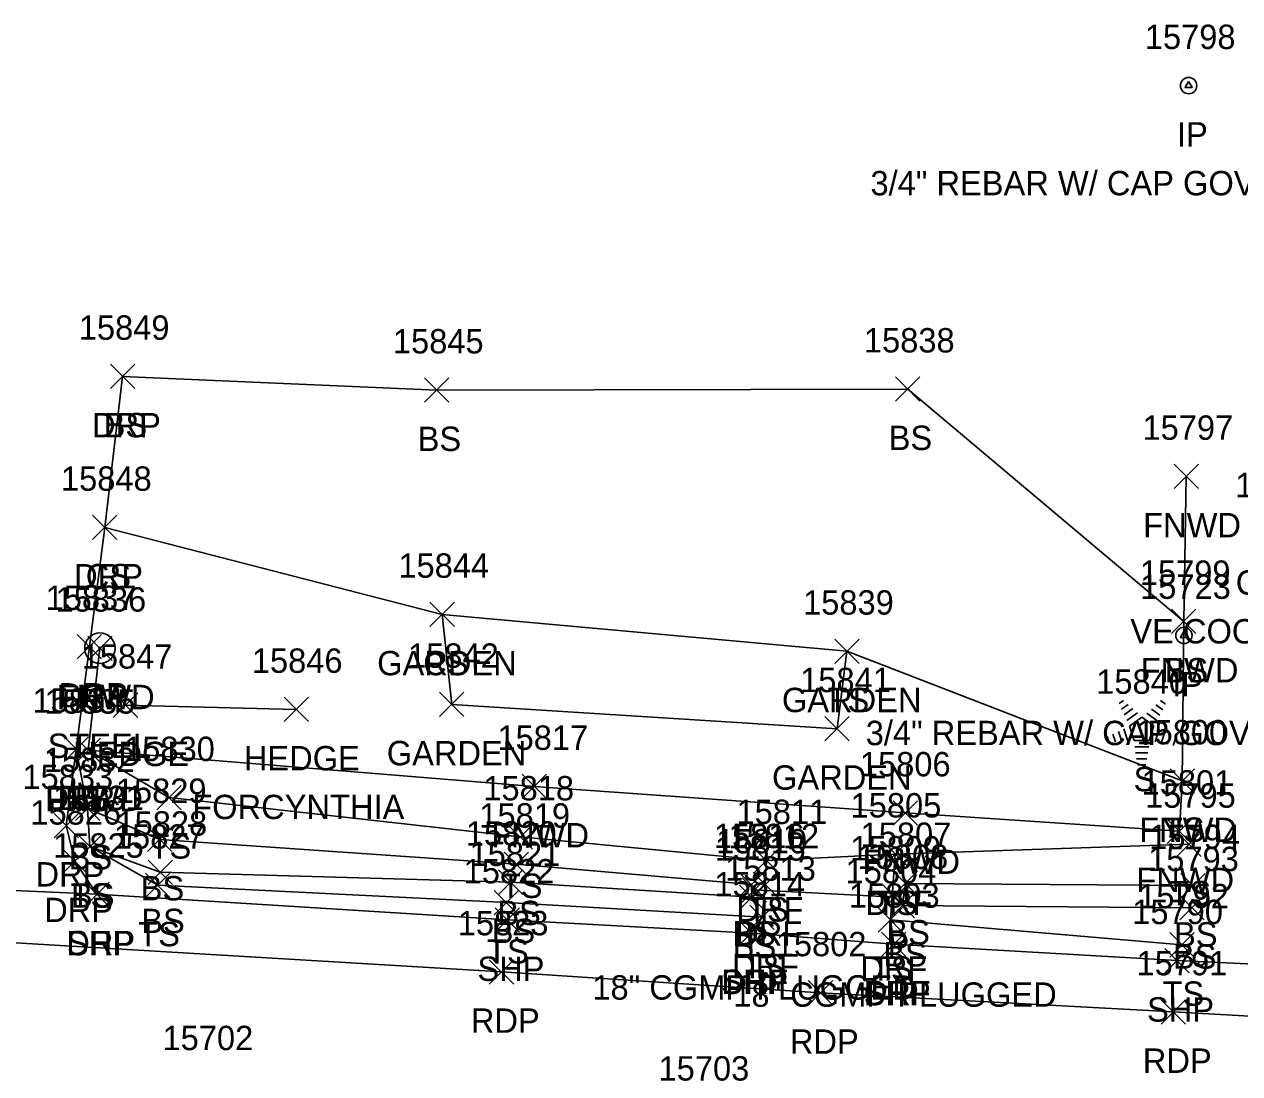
# Model space of a CAD drawing. Extents: x 1606530 to 1613020, y 784959 to 789666.
# Drawn here: x 1609586.7 to 1609686.4, y 788435.4 to 788521.5 of the extents above; entities that cross this region are included whole.
import ezdxf

# ---------------------------------------------------------------- set-up
doc = ezdxf.new("R2010")
doc.units = 0
for name, color, linetype in [('D_A', 7, 'Continuous'), ('D_C', 7, 'Continuous'), ('D_I', 7, 'Continuous'), ('D_TIC', 7, 'Continuous'), ('DCP', 7, 'Continuous'), ('L_A', 7, 'Continuous'), ('L_C', 7, 'Continuous'), ('L_I', 7, 'Continuous'), ('L_TIC', 7, 'Continuous'), ('LAHR', 7, 'Continuous'), ('LAPB', 7, 'Continuous'), ('LELB', 7, 'Continuous'), ('LFNC', 7, 'Continuous'), ('LTC', 7, 'Continuous'), ('M_A', 7, 'Continuous'), ('M_C', 7, 'Continuous'), ('M_I', 7, 'Continuous'), ('MPIR', 7, 'Continuous'), ('P_A', 7, 'Continuous'), ('P_I', 7, 'Continuous'), ('P_TIC', 7, 'Continuous'), ('PET', 7, 'Continuous'), ('PSP', 7, 'Continuous'), ('R_A', 7, 'Continuous'), ('R_I', 7, 'Continuous'), ('R_TIC', 7, 'Continuous'), ('RDF', 7, 'Continuous'), ('RDP', 7, 'Continuous'), ('RGP', 7, 'Continuous'), ('U_A', 7, 'Continuous'), ('U_C', 7, 'Continuous'), ('U_I', 7, 'Continuous')]:
    doc.layers.add(name, color=color, linetype=linetype)

msp = doc.modelspace()

# ---------------------------------------------------------------- linework, layer by layer
at = {"layer": 'D_TIC'}
for points in [[(1609645.563, 788449.455), (1609647.563, 788451.455)], [(1609647.563, 788449.455), (1609645.563, 788451.455)], [(1609657.117, 788448.869), (1609659.117, 788450.869)], [(1609659.117, 788448.869), (1609657.117, 788450.869)]]:
    msp.add_lwpolyline(points, dxfattribs=at)
at = {"layer": 'DCP'}
msp.add_lwpolyline([(1609658.117, 788449.869), (1609646.563, 788450.455)], dxfattribs=at)
at = {"layer": 'L_TIC'}
for points in [[(1609593.795, 788491.58), (1609595.795, 788493.58)], [(1609595.795, 788491.58), (1609593.795, 788493.58)], [(1609619.536, 788490.457), (1609621.536, 788492.457)], [(1609621.536, 788490.457), (1609619.536, 788492.457)], [(1609658.146, 788490.537), (1609660.146, 788492.537)], [(1609660.146, 788490.537), (1609658.146, 788492.537)], [(1609680.978, 788483.374), (1609682.978, 788485.374)], [(1609682.978, 788483.374), (1609680.978, 788485.374)], [(1609592.327, 788479.193), (1609594.327, 788481.193)], [(1609594.327, 788479.193), (1609592.327, 788481.193)], [(1609619.986, 788472.059), (1609621.986, 788474.059)], [(1609621.986, 788472.059), (1609619.986, 788474.059)], [(1609619.986, 788472.059), (1609621.986, 788474.059)], [(1609621.986, 788472.059), (1609619.986, 788474.059)], [(1609619.986, 788472.059), (1609621.986, 788474.059)], [(1609621.986, 788472.059), (1609619.986, 788474.059)], [(1609680.771, 788471.478), (1609682.771, 788473.478)], [(1609682.771, 788471.478), (1609680.771, 788473.478)], [(1609680.771, 788471.478), (1609682.771, 788473.478)], [(1609682.771, 788471.478), (1609680.771, 788473.478)], [(1609591.931, 788469.281), (1609593.931, 788471.281)], [(1609593.931, 788469.281), (1609591.931, 788471.281)], [(1609653.166, 788469.035), (1609655.166, 788471.035)], [(1609655.166, 788469.035), (1609653.166, 788471.035)], [(1609653.166, 788469.035), (1609655.166, 788471.035)], [(1609655.166, 788469.035), (1609653.166, 788471.035)], [(1609653.166, 788469.035), (1609655.166, 788471.035)], [(1609655.166, 788469.035), (1609653.166, 788471.035)], [(1609620.774, 788464.676), (1609622.774, 788466.676)], [(1609622.774, 788464.676), (1609620.774, 788466.676)], [(1609594.027, 788464.611), (1609596.027, 788466.611)], [(1609596.027, 788464.611), (1609594.027, 788466.611)], [(1609608.027, 788464.26), (1609610.027, 788466.26)], [(1609610.027, 788464.26), (1609608.027, 788466.26)], [(1609652.354, 788462.676), (1609654.354, 788464.676)], [(1609654.354, 788462.676), (1609652.354, 788464.676)], [(1609589.993, 788461.002), (1609591.993, 788463.002)], [(1609591.993, 788461.002), (1609589.993, 788463.002)], [(1609590.974, 788460.913), (1609592.974, 788462.913)], [(1609592.974, 788460.913), (1609590.974, 788462.913)], [(1609590.974, 788460.913), (1609592.974, 788462.913)], [(1609592.974, 788460.913), (1609590.974, 788462.913)], [(1609627.538, 788457.943), (1609629.538, 788459.943)], [(1609629.538, 788457.943), (1609627.538, 788459.943)], [(1609680.655, 788458.395), (1609682.655, 788460.395)], [(1609682.655, 788458.395), (1609680.655, 788460.395)], [(1609680.655, 788458.395), (1609682.655, 788460.395)], [(1609682.655, 788458.395), (1609680.655, 788460.395)], [(1609597.591, 788457.025), (1609599.591, 788459.025)], [(1609599.591, 788457.025), (1609597.591, 788459.025)], [(1609590.926, 788456.136), (1609592.926, 788458.136)], [(1609592.926, 788456.136), (1609590.926, 788458.136)], [(1609590.926, 788456.136), (1609592.926, 788458.136)], [(1609592.926, 788456.136), (1609590.926, 788458.136)], [(1609657.95, 788455.77), (1609659.95, 788457.77)], [(1609659.95, 788455.77), (1609657.95, 788457.77)], [(1609626.381, 788453.797), (1609628.381, 788455.797)], [(1609628.381, 788453.797), (1609626.381, 788455.797)], [(1609680.417, 788454.272), (1609682.417, 788456.272)], [(1609682.417, 788454.272), (1609680.417, 788456.272)], [(1609591.115, 788453.005), (1609593.115, 788455.005)], [(1609593.115, 788453.005), (1609591.115, 788455.005)], [(1609591.115, 788453.005), (1609593.115, 788455.005)], [(1609593.115, 788453.005), (1609591.115, 788455.005)], [(1609596.833, 788453.593), (1609598.833, 788455.593)], [(1609598.833, 788453.593), (1609596.833, 788455.593)], [(1609681.194, 788453.195), (1609683.194, 788455.195)], [(1609683.194, 788453.195), (1609681.194, 788455.195)], [(1609646.569, 788451.861), (1609648.569, 788453.861)], [(1609648.569, 788451.861), (1609646.569, 788453.861)], [(1609657.131, 788452.395), (1609659.131, 788454.395)], [(1609659.131, 788452.395), (1609657.131, 788454.395)], [(1609596.876, 788450.909), (1609598.876, 788452.909)], [(1609598.876, 788450.909), (1609596.876, 788452.909)], [(1609626.062, 788451.564), (1609628.062, 788453.564)], [(1609628.062, 788451.564), (1609626.062, 788453.564)], [(1609596.666, 788449.835), (1609598.666, 788451.835)], [(1609598.666, 788449.835), (1609596.666, 788451.835)], [(1609625.602, 788450.09), (1609627.602, 788452.09)], [(1609627.602, 788450.09), (1609625.602, 788452.09)], [(1609645.331, 788449.894), (1609647.331, 788451.894)], [(1609647.331, 788449.894), (1609645.331, 788451.894)], [(1609657.952, 788449.984), (1609659.952, 788451.984)], [(1609659.952, 788449.984), (1609657.952, 788451.984)], [(1609681.534, 788449.809), (1609683.534, 788451.809)], [(1609683.534, 788449.809), (1609681.534, 788451.809)], [(1609645.365, 788448.857), (1609647.365, 788450.857)], [(1609647.365, 788448.857), (1609645.365, 788450.857)], [(1609645.365, 788448.857), (1609647.365, 788450.857)], [(1609647.365, 788448.857), (1609645.365, 788450.857)], [(1609625.255, 788448.415), (1609627.255, 788450.415)], [(1609627.255, 788448.415), (1609625.255, 788450.415)], [(1609657.7, 788448.177), (1609659.7, 788450.177)], [(1609659.7, 788448.177), (1609657.7, 788450.177)], [(1609657.7, 788448.177), (1609659.7, 788450.177)], [(1609659.7, 788448.177), (1609657.7, 788450.177)], [(1609681.444, 788447.994), (1609683.444, 788449.994)], [(1609683.444, 788447.994), (1609681.444, 788449.994)], [(1609646.206, 788447.208), (1609648.206, 788449.208)], [(1609648.206, 788447.208), (1609646.206, 788449.208)], [(1609656.725, 788447), (1609658.725, 788449)], [(1609658.725, 788447), (1609656.725, 788449)], [(1609680.624, 788444.951), (1609682.624, 788446.951)], [(1609682.624, 788444.951), (1609680.624, 788446.951)]]:
    msp.add_lwpolyline(points, dxfattribs=at)
at = {"layer": 'LAHR'}
msp.add_lwpolyline([(1609609.027, 788465.26), (1609595.027, 788465.611)], dxfattribs=at)
at = {"layer": 'LAPB'}
for points in [[(1609654.166, 788470.035), (1609653.354, 788463.676), (1609621.774, 788465.676), (1609620.986, 788473.059)], [(1609654.166, 788470.035), (1609620.986, 788473.059)]]:
    msp.add_lwpolyline(points, dxfattribs=at)
at = {"layer": 'LELB'}
for points in [[(1609681.771, 788472.478), (1609659.146, 788491.537), (1609620.536, 788491.457), (1609594.795, 788492.58)], [(1609620.986, 788473.059), (1609593.327, 788480.193)], [(1609681.655, 788459.395), (1609654.166, 788470.035)], [(1609646.365, 788449.857), (1609626.602, 788451.09), (1609597.876, 788451.909), (1609592.115, 788454.005), (1609591.926, 788457.136), (1609590.993, 788462.002)], [(1609647.569, 788452.861), (1609627.381, 788454.797), (1609598.591, 788458.025), (1609591.974, 788461.913)], [(1609646.365, 788449.857), (1609646.331, 788450.894), (1609627.062, 788452.564), (1609597.833, 788454.593), (1609591.926, 788457.136)], [(1609647.206, 788448.208), (1609626.255, 788449.415), (1609597.666, 788450.835), (1609592.115, 788454.005)], [(1609682.194, 788454.195), (1609658.131, 788453.395)], [(1609682.534, 788450.809), (1609658.952, 788450.984), (1609658.7, 788449.177)], [(1609682.444, 788448.994), (1609658.7, 788449.177)], [(1609681.624, 788445.951), (1609657.725, 788448)]]:
    msp.add_lwpolyline(points, dxfattribs=at)
at = {"layer": 'LFNC'}
msp.add_lwpolyline([(1609681.978, 788484.374), (1609681.771, 788472.478), (1609681.655, 788459.395), (1609681.417, 788455.272), (1609658.95, 788456.77), (1609628.538, 788458.943), (1609591.974, 788461.913), (1609592.931, 788470.281)], dxfattribs=at)
at = {"layer": 'LTC'}
for p, q in [((1609676.47, 788465.748), (1609676.825, 788466.005)), ((1609676.68, 788465.282), (1609677.209, 788465.666)), ((1609679.869, 788465.988), (1609680.288, 788465.683)), ((1609676.889, 788464.816), (1609677.593, 788465.328)), ((1609677.099, 788464.35), (1609677.977, 788464.988)), ((1609678.755, 788464.943), (1609679.565, 788464.354)), ((1609679.127, 788465.291), (1609679.806, 788464.798)), ((1609679.497, 788465.64), (1609680.047, 788465.24)), ((1609676.869, 788463.676), (1609677.2, 788462.657)), ((1609677.324, 788463.895), (1609678.335, 788464.63)), ((1609677.324, 788463.895), (1609677.711, 788462.702)), ((1609678.335, 788464.63), (1609679.332, 788463.905)), ((1609679.332, 788463.905), (1609678.941, 788462.702)), ((1609675.503, 788463.027), (1609675.655, 788462.559)), ((1609675.958, 788463.243), (1609676.17, 788462.592)), ((1609676.414, 788463.46), (1609676.685, 788462.625)), ((1609678.941, 788462.702), (1609677.711, 788462.702)), ((1609679.77, 788463.634), (1609679.432, 788462.595)), ((1609680.214, 788463.384), (1609679.927, 788462.499)), ((1609680.659, 788463.134), (1609680.422, 788462.404)), ((1609681.103, 788462.883), (1609680.917, 788462.309)), ((1609678.903, 788462.202), (1609677.758, 788462.202)), ((1609678.819, 788461.702), (1609677.831, 788461.702)), ((1609678.735, 788461.202), (1609677.904, 788461.202)), ((1609678.652, 788460.702), (1609677.977, 788460.702))]:
    msp.add_line(p, q, dxfattribs=at)
at = {"layer": 'MPIR'}
for points in [[(1609682.172, 788516.762), (1609681.883, 788516.262), (1609682.46, 788516.262)], [(1609681.784, 788471.663), (1609681.495, 788471.163), (1609682.073, 788471.163)]]:
    msp.add_lwpolyline(points, close=True, dxfattribs=at)
for centre in [(1609682.172, 788516.429), (1609681.784, 788471.329)]:
    msp.add_circle(centre, 0.667, dxfattribs=at)
at = {"layer": 'P_TIC'}
for points in [[(1609591.684, 788449.096), (1609593.684, 788451.096)], [(1609593.684, 788449.096), (1609591.684, 788451.096)], [(1609625.337, 788446.989), (1609627.337, 788448.989)], [(1609627.337, 788446.989), (1609625.337, 788448.989)], [(1609645.319, 788445.917), (1609647.319, 788447.917)], [(1609647.319, 788445.917), (1609645.319, 788447.917)], [(1609656.996, 788444.994), (1609658.996, 788446.994)], [(1609658.996, 788444.994), (1609656.996, 788446.994)], [(1609680.225, 788443.652), (1609682.225, 788445.652)], [(1609682.225, 788443.652), (1609680.225, 788445.652)], [(1609624.849, 788442.733), (1609626.849, 788444.733)], [(1609626.849, 788442.733), (1609624.849, 788444.733)], [(1609650.997, 788441.015), (1609652.997, 788443.015)], [(1609652.997, 788441.015), (1609650.997, 788443.015)], [(1609679.929, 788439.448), (1609681.929, 788441.448)], [(1609681.929, 788439.448), (1609679.929, 788441.448)]]:
    msp.add_lwpolyline(points, dxfattribs=at)
at = {"layer": 'PET'}
msp.add_lwpolyline([(1609713.165, 788438.627), (1609680.929, 788440.448), (1609651.997, 788442.015), (1609625.849, 788443.733), (1609580.961, 788446.419), (1609565.084, 788447.467), (1609525.711, 788449.455), (1609486.159, 788451.542), (1609451.915, 788453.585), (1609423.874, 788454.943), (1609378.56, 788456.924), (1609332.013, 788457.666), (1609286.402, 788456.921), (1609233.035, 788453.523), (1609189.077, 788447.384), (1609175.759, 788445.193), (1609148.778, 788439.997), (1609127.707, 788434.803)], dxfattribs=at)
at = {"layer": 'PSP'}
msp.add_lwpolyline([(1609713.922, 788443.117), (1609681.225, 788444.652), (1609657.996, 788445.994), (1609646.319, 788446.917), (1609626.337, 788447.989), (1609592.684, 788450.096), (1609566.898, 788451.268), (1609526.223, 788453.589), (1609486.022, 788455.2), (1609451.52, 788457.024), (1609423.816, 788458.463), (1609378.085, 788460.467), (1609331.883, 788461.682), (1609285.229, 788461.605), (1609232.595, 788457.915), (1609188.508, 788451.364), (1609172.5, 788448.52), (1609147.32, 788443.745), (1609126.968, 788439.128), (1609114.118, 788436.455)], dxfattribs=at)
at = {"layer": 'R_TIC'}
for points in [[(1609593.795, 788491.58), (1609595.795, 788493.58)], [(1609595.795, 788491.58), (1609593.795, 788493.58)], [(1609592.327, 788479.193), (1609594.327, 788481.193)], [(1609594.327, 788479.193), (1609592.327, 788481.193)], [(1609591.073, 788469.419), (1609593.073, 788471.419)], [(1609593.073, 788469.419), (1609591.073, 788471.419)], [(1609589.993, 788461.002), (1609591.993, 788463.002)], [(1609591.993, 788461.002), (1609589.993, 788463.002)], [(1609589.167, 788454.734), (1609591.167, 788456.734)], [(1609591.167, 788454.734), (1609589.167, 788456.734)], [(1609589.874, 788451.812), (1609591.874, 788453.812)], [(1609591.874, 788451.812), (1609589.874, 788453.812)], [(1609646.569, 788451.861), (1609648.569, 788453.861)], [(1609648.569, 788451.861), (1609646.569, 788453.861)], [(1609657.131, 788452.395), (1609659.131, 788454.395)], [(1609659.131, 788452.395), (1609657.131, 788454.395)], [(1609646.472, 788449.879), (1609648.472, 788451.879)], [(1609648.472, 788449.879), (1609646.472, 788451.879)], [(1609591.684, 788449.096), (1609593.684, 788451.096)], [(1609593.684, 788449.096), (1609591.684, 788451.096)], [(1609646.206, 788447.208), (1609648.206, 788449.208)], [(1609648.206, 788447.208), (1609646.206, 788449.208)], [(1609656.725, 788447), (1609658.725, 788449)], [(1609658.725, 788447), (1609656.725, 788449)], [(1609645.319, 788445.917), (1609647.319, 788447.917)], [(1609647.319, 788445.917), (1609645.319, 788447.917)], [(1609656.996, 788444.994), (1609658.996, 788446.994)], [(1609658.996, 788444.994), (1609656.996, 788446.994)]]:
    msp.add_lwpolyline(points, dxfattribs=at)
at = {"layer": 'RDF'}
msp.add_lwpolyline([(1609657.996, 788445.994), (1609657.725, 788448), (1609658.131, 788453.395), (1609647.569, 788452.861), (1609647.472, 788450.879), (1609647.206, 788448.208), (1609646.319, 788446.917)], dxfattribs=at)
at = {"layer": 'RDP'}
msp.add_lwpolyline([(1609592.684, 788450.096), (1609590.874, 788452.812), (1609590.167, 788455.734), (1609590.993, 788462.002), (1609592.073, 788470.419), (1609593.327, 788480.193), (1609594.795, 788492.58)], dxfattribs=at)
at = {"layer": 'RGP'}
msp.add_line((1609592.931, 788470.281), (1609592.931, 788470.281), dxfattribs=at)
for radius in [1.25, 0.0833]:
    msp.add_circle((1609592.931, 788470.281), radius, dxfattribs=at)

# ---------------------------------------------------------------- texts
at = {"layer": 'D_A'}
for p in [(1609645.941, 788445.455), (1609657.495, 788444.869)]:
    msp.add_text('P', height=2, dxfattribs=at).set_placement(p)
at = {"layer": 'D_C'}
for p in [(1609633.296, 788441.455), (1609644.849, 788440.869)]:
    msp.add_text('18" CGMP PLUGGED', height=2, dxfattribs=at).set_placement(p)
at = {"layer": 'D_I'}
for s, p in [('15810', (1609643.453, 788453.455)), ('15809', (1609654.44, 788452.869))]:
    msp.add_text(s, height=2, dxfattribs=at).set_placement(p)
at = {"layer": 'L_A'}
for s, p in [('BS', (1609593.236, 788487.58)), ('BS', (1609618.977, 788486.457)), ('BS', (1609657.587, 788486.537)), ('FNWD', (1609678.443, 788479.374)), ('CS', (1609591.768, 788475.193)), ('GARDEN', (1609615.655, 788468.059)), ('GARDEN', (1609615.655, 788468.059)), ('CS', (1609619.427, 788468.059)), ('FNWD', (1609678.235, 788467.478)), ('BS', (1609680.212, 788467.478)), ('FNWD', (1609589.396, 788465.281)), ('GARDEN', (1609648.836, 788465.035)), ('GARDEN', (1609648.836, 788465.035)), ('TS', (1609652.576, 788465.035)), ('GARDEN', (1609616.443, 788460.676)), ('HEDGE', (1609590.728, 788460.611)), ('HEDGE', (1609604.728, 788460.26)), ('GARDEN', (1609648.023, 788458.676)), ('S', (1609677.661, 788458.539)), ('FNWD', (1609588.439, 788456.913)), ('BS', (1609589.434, 788457.002)), ('TS', (1609590.384, 788456.913)), ('FNWD', (1609625.002, 788453.943)), ('FNWD', (1609678.12, 788454.395)), ('TS', (1609680.065, 788454.395)), ('TS', (1609597, 788453.025)), ('BS', (1609590.367, 788452.136)), ('BS', (1609590.367, 788452.136)), ('FNWD', (1609655.415, 788451.77)), ('TS', (1609625.79, 788449.797)), ('FNWD', (1609677.882, 788450.272)), ('TS', (1609590.525, 788449.005)), ('BS', (1609590.556, 788449.005)), ('BS', (1609596.274, 788449.593)), ('TS', (1609680.604, 788449.195)), ('TS', (1609645.978, 788447.861)), ('TS', (1609656.541, 788448.395)), ('BS', (1609596.317, 788446.909)), ('BS', (1609625.503, 788447.564)), ('TS', (1609596.075, 788445.835)), ('BS', (1609625.043, 788446.09)), ('BS', (1609644.772, 788445.894)), ('BS', (1609657.393, 788445.984)), ('BS', (1609680.975, 788445.809)), ('BS', (1609644.806, 788444.857)), ('BS', (1609644.806, 788444.857)), ('TS', (1609624.664, 788444.415)), ('BS', (1609657.141, 788444.177)), ('BS', (1609657.141, 788444.177)), ('BS', (1609680.885, 788443.994)), ('TS', (1609645.616, 788443.208)), ('TS', (1609656.134, 788443)), ('TS', (1609680.033, 788440.951))]:
    msp.add_text(s, height=2, dxfattribs=at).set_placement(p)
at = {"layer": 'L_C'}
for s, p in [('STEEL', (1609588.648, 788461.281)), ('FORCYNTHIA', (1609600.5, 788456.26))]:
    msp.add_text(s, height=2, dxfattribs=at).set_placement(p)
at = {"layer": 'L_I'}
for s, p in [('15849', (1609591.197, 788495.58)), ('15838', (1609655.555, 788494.537)), ('15845', (1609616.945, 788494.457)), ('15797', (1609678.388, 788487.374)), ('15848', (1609589.737, 788483.193)), ('15844', (1609617.395, 788476.059)), ('15844', (1609617.395, 788476.059)), ('15844', (1609617.395, 788476.059)), ('15799', (1609678.173, 788475.478)), ('15799', (1609678.173, 788475.478)), ('15836', (1609589.286, 788473.281)), ('15839', (1609650.568, 788473.035)), ('15839', (1609650.568, 788473.035)), ('15839', (1609650.568, 788473.035)), ('15842', (1609618.184, 788468.676)), ('15847', (1609591.437, 788468.611)), ('15846', (1609605.382, 788468.26)), ('15841', (1609650.33, 788466.676)), ('15840', (1609674.598, 788466.539)), ('15834', (1609587.403, 788465.002)), ('15835', (1609588.384, 788464.913)), ('15835', (1609588.384, 788464.913)), ('15817', (1609625.515, 788461.943)), ('15800', (1609677.9, 788462.395)), ('15800', (1609677.9, 788462.395)), ('15830', (1609594.914, 788461.025)), ('15832', (1609588.335, 788460.136)), ('15832', (1609588.335, 788460.136)), ('15806', (1609655.226, 788459.77)), ('15818', (1609624.358, 788457.797)), ('15801', (1609678.315, 788458.272)), ('15831', (1609589.092, 788457.005)), ('15831', (1609589.092, 788457.005)), ('15829', (1609594.235, 788457.593)), ('15795', (1609678.604, 788457.195)), ('15811', (1609645.113, 788455.861)), ('15805', (1609654.462, 788456.395)), ('15828', (1609594.286, 788454.909)), ('15819', (1609624.031, 788455.564)), ('15827', (1609594.075, 788453.835)), ('15820', (1609622.925, 788454.09)), ('15816', (1609643.252, 788453.894)), ('15807', (1609655.283, 788453.984)), ('15794', (1609678.944, 788453.809)), ('15815', (1609643.342, 788452.857)), ('15815', (1609643.342, 788452.857)), ('15821', (1609623.231, 788452.415)), ('15808', (1609655.031, 788452.177)), ('15808', (1609655.031, 788452.177)), ('15793', (1609678.854, 788451.994)), ('15813', (1609644.183, 788451.208)), ('15804', (1609654.055, 788451)), ('15792', (1609678.034, 788448.951))]:
    msp.add_text(s, height=2, dxfattribs=at).set_placement(p)
at = {"layer": 'LTC'}
msp.add_text('.', height=1.037, rotation=270, dxfattribs=at).set_placement((1609678.218, 788463.643))
at = {"layer": 'M_A'}
for p in [(1609681.219, 788511.429), (1609680.831, 788466.329)]:
    msp.add_text('IP', height=2, dxfattribs=at).set_placement(p)
at = {"layer": 'M_C'}
for p in [(1609656.093, 788507.429), (1609655.706, 788462.329)]:
    msp.add_text('3/4" REBAR W/ CAP GOVE LS 475', height=2, dxfattribs=at).set_placement(p)
at = {"layer": 'M_I'}
for s, p in [('15798', (1609678.581, 788519.429)), ('15723', (1609678.194, 788474.329))]:
    msp.add_text(s, height=2, dxfattribs=at).set_placement(p)
at = {"layer": 'P_A'}
for s, p in [('SHP', (1609590.22, 788445.096)), ('SHP', (1609623.873, 788442.989)), ('SHP', (1609643.855, 788441.917)), ('SHP', (1609655.532, 788440.994)), ('SHP', (1609678.76, 788439.652)), ('RDP', (1609623.337, 788438.733)), ('RDP', (1609649.486, 788437.015)), ('RDP', (1609678.417, 788435.448))]:
    msp.add_text(s, height=2, dxfattribs=at).set_placement(p)
at = {"layer": 'P_I'}
for s, p in [('15825', (1609589.094, 788453.096)), ('15822', (1609622.747, 788450.989)), ('15814', (1609643.296, 788449.917)), ('15803', (1609654.327, 788448.994)), ('15823', (1609622.259, 788446.733)), ('15790', (1609677.548, 788447.652)), ('15802', (1609648.328, 788445.015)), ('15791', (1609677.906, 788443.448)), ('15702', (1609598.061, 788437.311)), ('15703', (1609638.721, 788434.817))]:
    msp.add_text(s, height=2, dxfattribs=at).set_placement(p)
at = {"layer": 'R_A'}
for s, p in [('DRP', (1609592.283, 788487.58)), ('DRP', (1609590.815, 788475.193)), ('DRP', (1609589.562, 788465.419)), ('GP', (1609591.365, 788465.281)), ('DRP', (1609588.481, 788457.002)), ('DRP', (1609587.655, 788450.734)), ('DRP', (1609588.362, 788447.812)), ('DRF', (1609645.104, 788447.861)), ('DRF', (1609655.667, 788448.395)), ('DRF', (1609645.008, 788445.879)), ('DRP', (1609590.173, 788445.096)), ('DRF', (1609644.741, 788443.208)), ('DRF', (1609655.26, 788443)), ('DRF', (1609643.855, 788441.917)), ('DRF', (1609655.532, 788440.994))]:
    msp.add_text(s, height=2, dxfattribs=at).set_placement(p)
at = {"layer": 'R_I'}
for s, p in [('15849', (1609591.197, 788495.58)), ('15848', (1609589.737, 788483.193)), ('15837', (1609588.483, 788473.419)), ('15836', (1609589.286, 788473.281)), ('15834', (1609587.403, 788465.002)), ('15833', (1609586.577, 788458.734)), ('15826', (1609587.228, 788455.812)), ('15811', (1609645.113, 788455.861)), ('15805', (1609654.462, 788456.395)), ('15812', (1609644.449, 788453.879)), ('15825', (1609589.094, 788453.096)), ('15813', (1609644.183, 788451.208)), ('15804', (1609654.055, 788451)), ('15814', (1609643.296, 788449.917)), ('15803', (1609654.327, 788448.994))]:
    msp.add_text(s, height=2, dxfattribs=at).set_placement(p)
at = {"layer": 'U_A'}
msp.add_text('COMB', height=2, dxfattribs=at).set_placement((1609686.033, 788474.669))
at = {"layer": 'U_C'}
msp.add_text('VE COOP 2F/6/1', height=2, dxfattribs=at).set_placement((1609677.396, 788470.669))
at = {"layer": 'U_I'}
msp.add_text('15796', height=2, dxfattribs=at).set_placement((1609686.002, 788482.669))

doc.saveas('drawing.dxf')
